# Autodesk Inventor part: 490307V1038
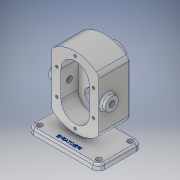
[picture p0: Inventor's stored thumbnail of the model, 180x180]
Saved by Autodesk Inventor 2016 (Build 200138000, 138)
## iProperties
Created: 2019-03
Part Number: 490307V1038
Material: 알루미늄 6061
Document SubType Name: Modeling
Designer: 605-11
Density: 2.7 g/cm^3
Appearance: 알루미늄 - 평지
Author: 605-11
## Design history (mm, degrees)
sketch "스케치1"
  geometry: L1 (50, 36.5)-(-50, 36.5); L2 (-60, 26.5)-(-60, -26.5); L3 (-50, -36.5)-(50, -36.5); L4 (60, -26.5)-(60, 26.5); L5 (60, 36.5)-(-60, -36.5); L6 (-60, 36.5)-(60, -36.5); C1 r 4.5 at (50, 26.5); C2 r 4.5 at (50, -26.5); C3 r 4.5 at (-50, -26.5); C4 r 4.5 at (-50, 26.5); A1 r 10 centre (50, 26.5) between (60, 26.5) and (50, 36.5); A2 r 10 centre (50, -26.5) between (50, -36.5) and (60, -26.5); A3 r 10 centre (-50, 26.5) between (-50, 36.5) and (-60, 26.5); A4 r 10 centre (-50, -26.5) between (-60, -26.5) and (-50, -36.5); 1 further point
  constraints: 12 end point, 8 centre point, 8 point on circle, 8 point on line, 8 tangent, 4 coincident, 3 equal radius, 2 midpoint, 2 parallel, 1 horizontal, 1 perpendicular
  dimensions: "d0" = 73 distance of L6.end L5.start; "d1" = 120 distance of L5.start L6.start; "d2" = 10 radius of A1; "d3" = 9 diameter of C1; "d4" = 9 diameter of C2; "d5" = 9 diameter of C3; "d6" = 9 diameter of C4
extrude "돌출1" new body sketch "스케치1" distance "d7" = 10; taper "d8" = 0 deg
sketch "스케치2"
  geometry: L1 (10, -108)-(10, -28); L2 (90, -28)-(90, -108); L3 (0, 0)-(100, 0) reference; L4 (90, -68)-(10, -68); L5 (0, 10)-(100, 10) reference; A1 r 60 centre (50, -68) between (86, -20) and (14, -20); A2 r 60 centre (50, -68) between (14, -116) and (86, -116); A3 r 10 centre (80, -108) between (86, -116) and (90, -108); A4 r 10 centre (20, -108) between (10, -108) and (14, -116); A5 r 10 centre (20, -28) between (14, -20) and (10, -28); A6 r 10 centre (80, -28) between (90, -28) and (86, -20); 7 further points
  constraints: 16 point on circle, 8 tangent, 6 centre point, 6 end point, 4 midpoint, 4 point on line, 3 equal radius, 1 parallel, 1 vertical alignment
  dimensions: "d10" = 78 distance from line of L5 L4.start; "d14" = 80 distance between parallel lines of L1 L2; "d15" = 10 radius of A3
extrude "돌출2" join sketch "스케치2" distance "d16" = 53; taper "d17" = 0 deg
sketch "스케치3"
  geometry: L1 (0, 0)-(100, 0) reference; L2 (56, 0)-(44, 0); L3 (44, 0)-(44, -12.849); L4 (44, -12.849)-(56, -12.849); L5 (56, -12.849)-(56, 0); 3 further points
  constraints: 8 end point, 2 midpoint, 2 parallel, 1 horizontal, 1 perpendicular, 1 point on line, 1 vertical alignment
  dimensions: "d18" = 12 distance of L3.end L4.end
extrude "돌출3" join sketch "스케치3" distance "d19" = 43; taper "d20" = 0 deg
sketch "스케치4"
  geometry: L1 (-10, -28)-(-10, -108) reference; L2 (-90, -108)-(-90, -28) reference; L3 (10, 10)-(10, 0) reference; L4 (10, 0)-(-110, 0) reference; L5 (-110, 0)-(-110, 10) reference; L6 (-110, 10)-(10, 10) reference; L7 (-50, -90)-(-50, -46); L8 (-26, -90)-(-26, -46); L9 (-74, -46)-(-74, -90); L10 (-100, 0)-(0, 0) reference; A1 r 60 centre (-50, -68) between (-14, -20) and (-86, -20) reference; A2 r 10 centre (-20, -28) between (-10, -28) and (-14, -20) reference; A3 r 10 centre (-20, -108) between (-14, -116) and (-10, -108) reference; A4 r 60 centre (-50, -68) between (-86, -116) and (-14, -116) reference; A5 r 10 centre (-80, -108) between (-90, -108) and (-86, -116) reference; A6 r 10 centre (-80, -28) between (-86, -20) and (-90, -28) reference; A7 r 24 centre (-50, -90) between (-74, -90) and (-26, -90); A8 r 24 centre (-50, -46) between (-26, -46) and (-74, -46); 3 further points
  constraints: 8 end point, 4 point on circle, 4 tangent, 2 centre point, 2 midpoint, 1 coincident, 1 parallel, 1 vertical, 1 vertical alignment
  dimensions: "d21" = 44 distance of L7.start L7.end; "d22" = 48 diameter of A8
extrude "돌출4" cut sketch "스케치4" distance "d24" = 29; taper "d25" = 0 deg
node "작업 평면1"
sketch "스케치5"
  geometry: L1 (-10, 22.469)-(0, 22.469) reference; L2 (0, 22.469)-(0, -22.469) reference; L3 (0, -22.469)-(-10, -22.469) reference; L4 (-10, -22.469)-(-10, 22.469) reference; L5 (0, -36.5)-(-10, -36.5) reference; L6 (-10, -36.5)-(-10, -30.531) reference; L7 (-10, -30.531)-(0, -30.531) reference; L8 (0, -30.531)-(0, -36.5) reference; L9 (-10, 36.5)-(0, 36.5) reference; L10 (0, 36.5)-(0, 30.531) reference; L11 (0, 30.531)-(-10, 30.531) reference; L12 (-10, 30.531)-(-10, 36.5) reference; L13 (108, -36.5)-(28, -36.5) reference; L14 (108, -36.5)-(108, 16.5) reference; L15 (28, 16.5)-(108, 16.5) reference; L16 (28, -36.5)-(28, 16.5) reference; L17 (-10, -26.5)-(-10, 26.5) reference; C1 r 11 at (68, 2.5); 2 further points
  constraints: 1 centre point, 1 midpoint, 1 vertical alignment
  dimensions: "d27" = 22 diameter of C1; "d28" = 14 distance from line of L15 C1.centre; "d29" = 78 distance from line of L17 C1.centre (derived)
extrude "돌출5" join sketch "스케치5" stored distance "d30" = 29; taper "d31" = 0 deg
hole "구멍1" diameter "d34" = 10; stored, may be unused: countersink angle "d38" = 90 deg, drill point angle "d40" = 0 deg; dims "d35" = 20, "d36" = 4, "d37" = 2, "d39" = 25.1, "d89" = 10, "d90" = 10
sketch "스케치6"
  geometry: L1 (-100, 0)-(0, 0) reference; L2 (-50, -90)-(-50, -46); L3 (-74, -46)-(-74, -90) reference; L4 (-26, -90)-(-26, -46) reference; L5 (10, 10)-(10, 0) reference; L6 (10, 0)-(-44, 0) reference; L7 (-44, 0)-(-44, -8.301) reference; L8 (-10, -28)-(-10, -108) reference; L9 (-90, -108)-(-90, -28) reference; L10 (-56, -8.301)-(-56, 0) reference; L11 (-56, 0)-(-110, 0) reference; L12 (-110, 0)-(-110, 10) reference; L13 (-110, 10)-(10, 10) reference; L14 (-26, -46)-(-26, -90) reference; C1 r 12.5 at (-50, -46); C2 r 12.5 at (-50, -90); A1 r 24 centre (-50, -90) between (-74, -90) and (-26, -90) reference; A2 r 24 centre (-50, -46) between (-26, -46) and (-74, -46) reference; A3 r 60 centre (-50, -68) between (-14, -20) and (-44, -8.301) reference; A4 r 10 centre (-20, -28) between (-10, -28) and (-14, -20) reference; A5 r 10 centre (-20, -108) between (-14, -116) and (-10, -108) reference; A6 r 60 centre (-50, -68) between (-86, -116) and (-14, -116) reference; A7 r 10 centre (-80, -108) between (-90, -108) and (-86, -116) reference; A8 r 10 centre (-80, -28) between (-86, -20) and (-90, -28) reference; A9 r 60 centre (-50, -68) between (-56, -8.301) and (-86, -20) reference; 5 further points
  constraints: 4 midpoint, 2 centre point, 2 end point, 2 vertical alignment, 1 horizontal alignment, 1 vertical
  dimensions: "d42" = 25 diameter of C1; "d43" = 25 diameter of C2; "d44" = 44 distance of L2.start L2.end
extrude "돌출6" cut sketch "스케치6" distance "d45" = 15; taper "d46" = 0 deg
node "작업 평면3"
sketch "스케치7"
  geometry: L1 (0, -10)-(0, 0) reference; L2 (0, 0)-(100, 0) reference; L3 (100, -10)-(100, 0) reference; L4 (100, -10)-(56, -10) reference; L5 (56, -10)-(56, -18.301) reference; L6 (90, -38)-(90, -118) reference; L7 (10, -118)-(10, -38) reference; L8 (44, -18.301)-(44, -10) reference; L9 (44, -10)-(0, -10) reference; L10 (0, -10)-(44, -10) reference; L11 (44, -10)-(44, -18.301) reference; L12 (10, -38)-(10, -118) reference; L13 (90, -118)-(90, -38) reference; L14 (56, -18.301)-(56, -10) reference; L15 (56, -10)-(100, -10) reference; L16 (100, -10)-(100, 0) reference; L17 (0, 0)-(100, 0) reference; L18 (0, -10)-(0, 0) reference; C1 r 12.5 at (50, -100) reference; C2 r 19 at (50, -100); A1 r 60 centre (50, -78) between (86, -30) and (56, -18.301) reference; A2 r 10 centre (80, -38) between (90, -38) and (86, -30) reference; A3 r 10 centre (80, -118) between (86, -126) and (90, -118) reference; A4 r 60 centre (50, -78) between (14, -126) and (86, -126) reference; A5 r 10 centre (20, -118) between (10, -118) and (14, -126) reference; A6 r 10 centre (20, -38) between (14, -30) and (10, -38) reference; A7 r 60 centre (50, -78) between (44, -18.301) and (14, -30) reference; A8 r 60 centre (50, -78) between (44, -18.301) and (14, -30) reference; A9 r 10 centre (20, -38) between (14, -30) and (10, -38) reference; A10 r 10 centre (20, -118) between (10, -118) and (14, -126) reference; A11 r 60 centre (50, -78) between (14, -126) and (86, -126) reference; A12 r 10 centre (80, -118) between (86, -126) and (90, -118) reference; A13 r 10 centre (80, -38) between (90, -38) and (86, -30) reference; A14 r 60 centre (50, -78) between (86, -30) and (56, -18.301) reference; 1 further point
  constraints: 1 centre point, 1 coincident
  dimensions: "d47" = 38 diameter of C2
extrude "돌출7" join sketch "스케치7" distance "d48" = 17; taper "d49" = 0 deg
hole "구멍2" diameter "d52" = 17; stored, may be unused: countersink angle "d56" = 90 deg, drill point angle "d58" = 0 deg; dims "d50" = 10, "d51" = 10, "d53" = 20, "d54" = 4, "d55" = 2, "d57" = 25.1
hole "구멍3" diameter "d61" = 28; stored, may be unused: countersink angle "d65" = 90 deg, drill point angle "d67" = 0 deg; dims "d59" = 10, "d60" = 10, "d62" = 20, "d63" = 4, "d64" = 2, "d66" = 7.3
sketch "스케치8"
  geometry: L1 (-26, -46)-(-26, -90) reference; L2 (-74, -90)-(-74, -46) reference; L3 (-90, -28)-(-90, -108) reference; L4 (-10, -108)-(-10, -28) reference; L5 (-19, -90)-(-19, -46); L6 (-81, -90)-(-81, -46); C1 r 8.5 at (-50, -90) reference; A1 r 24 centre (-50, -46) between (-26, -46) and (-74, -46) reference; A2 r 24 centre (-50, -90) between (-74, -90) and (-26, -90) reference; A3 r 10 centre (-80, -108) between (-90, -108) and (-86, -116) reference; A4 r 60 centre (-50, -68) between (-86, -116) and (-14, -116) reference; A5 r 10 centre (-20, -108) between (-14, -116) and (-10, -108) reference; A6 r 10 centre (-20, -28) between (-10, -28) and (-14, -20) reference; A7 r 60 centre (-50, -68) between (-14, -20) and (-86, -20) reference; A8 r 10 centre (-80, -28) between (-86, -20) and (-90, -28) reference; A9 r 31 centre (-50, -46) between (-28.16, -68) and (-26, -65.621); A10 r 31 centre (-50, -90) between (-26, -70.379) and (-28.16, -68); A11 r 31 centre (-50, -46) between (-19, -46) and (-81, -46); A12 r 31 centre (-50, -46) between (-74, -65.621) and (-71.84, -68); A13 r 31 centre (-50, -90) between (-71.84, -68) and (-74, -70.379); A14 r 31 centre (-50, -90) between (-81, -90) and (-19, -90); 7 further points
  constraints: 14 point on circle, 6 centre point, 6 coincident, 4 end point, 4 horizontal alignment, 4 point on line, 3 tangent, 2 vertical alignment, 1 vertical
hole "구멍4" sketch "스케치8" at (-50, -121), (-50, -15), (-19, -46), (-81, -46), (-81, -90), (-19, -90) diameter "d70" = 4.459; stored, may be unused: countersink angle "d74" = 90 deg, drill point angle "d76" = 118 deg; dims "d71" = 10, "d72" = 4, "d73" = 2, "d75" = 12
chamfer "모따기1" distance "d77" = 0.7; stored, may be unused: second distance "d78" = 2, angle "d79" = 30 deg
fillet "모깎기2" dims "d80" = 0.5
fillet "모깎기3" dims "d81" = 3
sketch "스케치9"
  geometry: L1 (50, 36.5)-(-50, 36.5) reference; L2 (60, -26.5)-(60, 26.5) reference; 2 further points
  constraints: 1 other
  dimensions: "d82" = 10 distance from line of L1 point (0, 26.5); "d83" = 60 distance from line of L2 point (0, 26.5)
feature "엠보싱1" sketch "스케치9" dims "d0" = 73, "d1" = 120, "d2" = 10, "d3" = 9, "d4" = 9, "d5" = 9, "d6" = 9, "d84" = 0.5, "d85" = 0
chamfer "모따기2" distance "d86" = 1; stored, may be unused: second distance "d87" = 2, angle "d88" = 30 deg
feature "스레드1" dims "d91" = 10, "d92" = 0
feature "스레드2" dims "d93" = 10, "d94" = 0
node "솔리드1"
mirror "대칭1"
node "투영된 루프1"
node "투영된 루프2"
node "투영된 루프3"
node "절단 모서리 투영1"
node "절단 모서리 투영2"
node "절단 모서리 투영3"
node "절단 모서리 투영4"
other parameters: "d26" = -48, "d68" = 62, "d69" = 62
